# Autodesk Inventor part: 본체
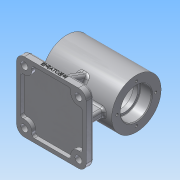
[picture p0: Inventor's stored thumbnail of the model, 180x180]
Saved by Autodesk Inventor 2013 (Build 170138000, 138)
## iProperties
Created: 2019-06
Part Number: 본체
Material: 알루미늄 6061
Document SubType Name: Modeling
Designer: Administrator
Density: 2.71 g/cm^3
Mass: 612.634 g
Surface Area: 622.719 cm^2
Volume: 226.064 cm^3
Author: Administrator
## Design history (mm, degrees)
sketch "스케치1"
  geometry: L1 (0, 0)-(45, 0); L2 (45, 0)-(45, 32); L3 (45, 32)-(0, 32); L4 (0, 32)-(0, 0); L5 (45, 20)-(30, 20); L6 (30, 20)-(30, 17); L7 (30, 17)-(24, 17); L8 (24, 17)-(24, 25); L9 (24, 25)-(0, 25); 1 further point
  constraints: 18 end point, 5 perpendicular, 3 parallel, 2 point on line, 1 coincident, 1 horizontal
  dimensions: "d6" = 45 distance of L1.start L1.end; "d7" = 64 diameter of L3 L1; "d8" = 50 diameter of L9 L1; "d9" = 40 diameter of L5 L1; "d10" = 34 diameter of L7 L1; "d11" = 15 distance of L5.start L5.end; "d12" = 24 distance of L8.end L9.end
revolve "회전1" sketch "스케치1" stored, may be unused: angle "d13" = 90 deg
sketch "스케치2"
  geometry: C1 r 20 at (0, 0) reference; 1 further point
  constraints: 1 vertical alignment
  dimensions: "d14" = 25 distance of point (0, 25) C1.centre
hole "구멍1" sketch "스케치2" at (0, 25) diameter "d15" = 3.242; stored, may be unused: countersink angle "d19" = 90 deg, drill point angle "d21" = 118 deg; dims "d16" = 7, "d17" = 4, "d18" = 2, "d20" = 9
chamfer "모따기1" distance "d25" = 1; stored, may be unused: second distance "d26" = 2, angle "d27" = 45 deg
fillet "모깎기1" dims "d28" = 0.6
fillet "모깎기2" dims "d29" = 3
node "작업 평면2"
sketch "스케치3" dims "d35" = 10
  geometry: L1 (45, -45)-(-45, -45); L2 (-45, -45)-(-45, 45); L3 (-45, 45)-(45, 45); L4 (45, 45)-(45, -45); L5 (45, -45)-(-45, 45); L6 (-45, -45)-(45, 45); L7 (35, -5)-(-35, -5); L8 (-35, -5)-(-35, 5); L9 (-35, 5)-(35, 5); L10 (35, 5)-(35, -5); L11 (35, -5)-(-35, 5); L12 (-35, -5)-(35, 5); L13 (-40, 40)-(40, 40); L14 (40, 40)-(40, -40); L15 (40, -40)-(-40, -40); L16 (-40, -40)-(-40, 40); L17 (-40, -40)-(-30, -40); L18 (-40, -30)-(-40, -40); L19 (40, -40)-(30, -40); L20 (40, -30)-(40, -40); A1 r 10 centre (-35, 35) between (-40, 26.34) and (-26.34, 40); A2 r 10 centre (35, 35) between (26.34, 40) and (40, 26.34); 7 further points
  constraints: 40 end point, 8 midpoint, 6 parallel, 5 horizontal, 4 point on circle, 4 point on line, 3 coincident, 3 perpendicular, 2 centre point, 2 horizontal alignment, 1 vertical alignment
  dimensions: "d31" = 90 distance of L2.end L3.end; "d32" = 90 distance of L1.end L2.end; "d33" = 70 distance of L8.end L9.end; "d34" = 10 distance of L7.end L8.end; "d54" = 80 distance of L14.end L15.end; "d55" = 80 distance of L13.end L14.end; "d62" = 10 distance from line of point (-35, 35) L2; "d63" = 10 distance from line of point (-35, 35) L3; "d64" = 10 distance from line of point (35, 35) L4; "d68" = 10 radius of A1; "d70" = 10 radius of A2
extrude "돌출1" join sketch "스케치3" distance "d35" = 10; taper "d36" = 0 deg
extrude "돌출2" join sketch "스케치3" stored distance "d37" = 10; taper "d38" = 0 deg
node "작업 평면3"
sketch "스케치4"
  geometry: C1 r 5 at (0, 0); 1 further point
  constraints: 1 centre point, 1 coincident
  dimensions: "d40" = 10 diameter of C1
extrude "돌출3" join sketch "스케치4" stored distance "d41" = 10; taper "d42" = 0 deg
fillet "모깎기3" dims "d43" = 2
sketch "스케치5"
  geometry: L1 (-55, 35)-(-44.813, 31.292); L2 (-55, 45)-(-55, -45) reference; L3 (-65, 45)-(-55, 45) reference; 1 further point
  constraints: 2 end point, 1 point on line
  dimensions: "d44" = 110 deg angle of L1 L2; "d45" = 10 distance from line of L1.start L3
feature "리브1" sketch "스케치5" dims "d46" = 1, "d47" = 10, "d48" = 0, "d49" = 0, "d50" = 1, "d51" = 1
fillet "모깎기4" dims "d52" = 10
fillet "모깎기5" dims "d53" = 3
extrude "돌출4" cut sketch "스케치3" distance "d60" = 5; taper "d61" = 0 deg
extrude "돌출5" join sketch "스케치3" distance "d65" = 5; taper "d66" = 0 deg
extrude "돌출6" cut sketch "스케치3" distance "d75" = 5; taper "d76" = 0 deg
extrude "돌출7" join sketch "스케치3" distance "d77" = 5; taper "d78" = 0 deg
fillet "모깎기6" dims "d79" = 3
hole "구멍2" sketch "스케치3" diameter "d80" = 9; stored, may be unused: countersink angle "d84" = 90 deg, drill point angle "d86" = 0 deg; dims "d81" = 7, "d82" = 4, "d83" = 2, "d85" = 10
fillet "모깎기7" dims "d87" = 3
fillet "모깎기8" dims "d88" = 3
fillet "모깎기9" dims "d89" = 3
hole "구멍3" diameter "d92" = 4.917; stored, may be unused: countersink angle "d96" = 90 deg, drill point angle "d98" = 0 deg; dims "d90" = 10, "d91" = 10, "d93" = 7, "d94" = 4, "d95" = 2, "d97" = 10
sketch "스케치6"
  geometry: L1 (0, 0)-(-10, 0) reference; 2 further points
  constraints: 1 other
  dimensions: "d99" = 4 distance from line of point (35, 4) L1; "d100" = 45 horizontal distance of point (35, 4) L1.end
feature "엠보싱1" sketch "스케치6" dims "d6" = 45, "d7" = 64, "d8" = 50, "d9" = 40, "d10" = 34, "d11" = 15, "d12" = 24, "d101" = 0.5, "d102" = 0
node "솔리드1"
pattern_circular "원형 패턴1" dims angle "d23" = 360 deg
mirror "대칭1"
mirror "대칭2"
mirror "대칭3"
other parameters: "d30" = -65
